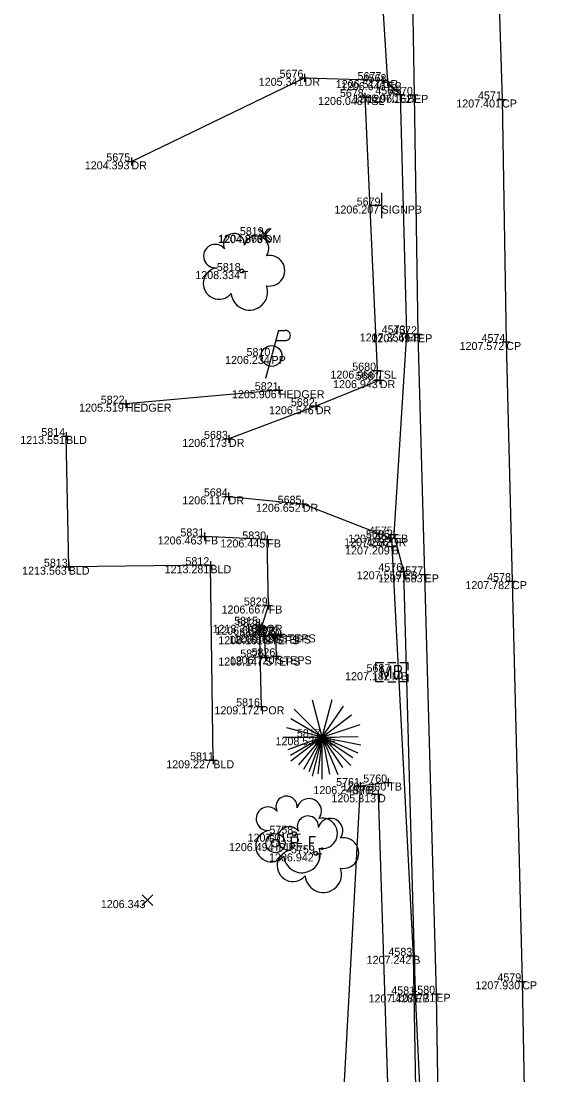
# Model space of a CAD drawing. Extents: x 2044996 to 2050343, y 455232 to 458054.
# Drawn here: x 2047573.4 to 2047639.7, y 456784 to 456915.7 of the extents above; entities that cross this region are included whole.
import ezdxf

# ---------------------------------------------------------------- set-up
doc = ezdxf.new("R2010")
doc.units = 0
for name, color, linetype in [('BD_X_Building', 7, 'Continuous'), ('BD_X_Porch_or_Deck', 7, 'Continuous'), ('DR_X_Ditch', 7, 'Continuous'), ('DT_X_Contour_Minor', 7, 'Continuous'), ('DT_X_Contour_Text', 7, 'Continuous'), ('DT_X_Island', 7, 'Continuous'), ('DT_X_Spot_Elev', 7, 'Continuous'), ('DT_X_Triangles', 7, 'Continuous'), ('DT_X_Void', 7, 'Continuous'), ('PV_X_COP', 7, 'Continuous'), ('PV_X_Driveway', 7, 'Continuous'), ('PV_X_EOP', 7, 'Continuous'), ('PV_X_Shoulder_Aggregate', 7, 'Continuous'), ('PV_X_Steps', 7, 'Continuous'), ('RD_X_Cells', 7, 'Continuous'), ('SN_X_Public', 7, 'Continuous'), ('SV_X_Break_Lines', 7, 'Continuous'), ('SV_X_Toe_of_Slope', 7, 'Continuous'), ('SV_X_Top_of_Bank', 7, 'Continuous'), ('UT_X_Electric_Cells', 7, 'Continuous'), ('VG_X_Cells', 7, 'Continuous'), ('VG_X_Flower_Bed', 7, 'Continuous'), ('VG_X_Shrub_Line_Lt', 7, 'Continuous'), ('XS_X_Ground_Line', 7, 'Continuous')]:
    doc.layers.add(name, color=color, linetype=linetype)

msp = doc.modelspace()

# ---------------------------------------------------------------- linework, layer by layer
at = {"layer": 'BD_X_Building'}
msp.add_lwpolyline([(2047597.43, 456823.32), (2047597.07, 456847.69), (2047579.37, 456847.51), (2047579.04, 456863.84)], dxfattribs=at)
at = {"layer": 'BD_X_Porch_or_Deck'}
msp.add_lwpolyline([(2047603.17, 456840.25), (2047603.41, 456830.06)], dxfattribs=at)
at = {"layer": 'DR_X_Ditch'}
msp.add_lwpolyline([(2047618, 456819.07), (2047619.27, 456780.34), (2047618.87, 456740.62)], dxfattribs=at)
at = {"layer": 'DT_X_Island'}
msp.add_circle((2047603.85, 456888.94), 0.2, dxfattribs=at)
msp.add_arc((2047604.65, 456888.94), 0.8, 90, 270, dxfattribs=at)
at = {"layer": 'DT_X_Spot_Elev'}
for p, q in [((2047603.23, 456888.33), (2047604.57, 456889.67)), ((2047603.23, 456889.67), (2047604.57, 456888.33)), ((2047588.54, 456805.19), (2047589.87, 456806.52)), ((2047588.54, 456806.52), (2047589.87, 456805.19))]:
    msp.add_line(p, q, dxfattribs=at)
at = {"layer": 'DT_X_Void'}
for p, q in [((2047608.83, 456909.1), (2047608.83, 456908.1)), ((2047618.6, 456908.81), (2047618.6, 456907.81)), ((2047608.33, 456908.6), (2047609.33, 456908.6)), ((2047608.83, 456908.6), (2047608.83, 456908.6)), ((2047618.1, 456908.31), (2047619.1, 456908.31)), ((2047618.6, 456908.31), (2047618.6, 456908.31)), ((2047618.7, 456908.05), (2047619.7, 456908.05)), ((2047619.2, 456908.55), (2047619.2, 456907.55)), ((2047619.2, 456908.05), (2047619.2, 456908.05)), ((2047615.86, 456906.2), (2047616.86, 456906.2)), ((2047616.36, 456906.7), (2047616.36, 456905.7)), ((2047616.36, 456906.2), (2047616.36, 456906.2)), ((2047620.26, 456906.51), (2047621.26, 456906.51)), ((2047620.76, 456907.01), (2047620.76, 456906.01)), ((2047620.76, 456906.51), (2047620.76, 456906.51)), ((2047622, 456906.46), (2047623, 456906.46)), ((2047622.5, 456906.96), (2047622.5, 456905.96)), ((2047622.5, 456906.46), (2047622.5, 456906.46)), ((2047633.49, 456906.39), (2047633.49, 456905.39)), ((2047632.99, 456905.89), (2047633.99, 456905.89)), ((2047633.49, 456905.89), (2047633.49, 456905.89)), ((2047586.7, 456898.16), (2047587.7, 456898.16)), ((2047587.2, 456898.66), (2047587.2, 456897.66)), ((2047587.2, 456898.16), (2047587.2, 456898.16)), ((2047621.56, 456877.15), (2047621.56, 456876.15)), ((2047622.99, 456877.05), (2047622.99, 456876.05)), ((2047621.06, 456876.65), (2047622.06, 456876.65)), ((2047621.56, 456876.65), (2047621.56, 456876.65)), ((2047622.49, 456876.55), (2047623.49, 456876.55)), ((2047622.99, 456876.55), (2047622.99, 456876.55)), ((2047634.02, 456876.09), (2047634.02, 456875.09)), ((2047633.52, 456875.59), (2047634.52, 456875.59)), ((2047634.02, 456875.59), (2047634.02, 456875.59)), ((2047617.4, 456872.01), (2047618.4, 456872.01)), ((2047617.9, 456872.51), (2047617.9, 456871.51)), ((2047617.9, 456872.01), (2047617.9, 456872.01)), ((2047617.72, 456870.82), (2047618.72, 456870.82)), ((2047618.22, 456871.32), (2047618.22, 456870.32)), ((2047618.22, 456870.82), (2047618.22, 456870.82)), ((2047605.1, 456869.56), (2047606.1, 456869.56)), ((2047605.6, 456870.06), (2047605.6, 456869.06)), ((2047605.6, 456869.56), (2047605.6, 456869.56)), ((2047585.99, 456867.88), (2047586.99, 456867.88)), ((2047586.49, 456868.38), (2047586.49, 456867.38)), ((2047586.49, 456867.88), (2047586.49, 456867.88)), ((2047610.23, 456868.06), (2047610.23, 456867.06)), ((2047609.73, 456867.56), (2047610.73, 456867.56)), ((2047610.23, 456867.56), (2047610.23, 456867.56)), ((2047579.04, 456864.34), (2047579.04, 456863.34)), ((2047599.38, 456863.98), (2047599.38, 456862.98)), ((2047578.54, 456863.84), (2047579.54, 456863.84)), ((2047579.04, 456863.84), (2047579.04, 456863.84)), ((2047598.88, 456863.48), (2047599.88, 456863.48)), ((2047599.38, 456863.48), (2047599.38, 456863.48)), ((2047598.84, 456856.3), (2047599.84, 456856.3)), ((2047599.34, 456856.8), (2047599.34, 456855.8)), ((2047599.34, 456856.3), (2047599.34, 456856.3)), ((2047608.1, 456855.37), (2047609.1, 456855.37)), ((2047608.6, 456855.87), (2047608.6, 456854.87)), ((2047608.6, 456855.37), (2047608.6, 456855.37)), ((2047595.82, 456851.29), (2047596.82, 456851.29)), ((2047596.32, 456851.79), (2047596.32, 456850.79)), ((2047596.32, 456851.29), (2047596.32, 456851.29)), ((2047603.67, 456850.91), (2047604.67, 456850.91)), ((2047604.17, 456851.41), (2047604.17, 456850.41)), ((2047604.17, 456850.91), (2047604.17, 456850.91)), ((2047619.11, 456851.07), (2047620.11, 456851.07)), ((2047619.49, 456851.52), (2047620.49, 456851.52)), ((2047619.61, 456851.57), (2047619.61, 456850.57)), ((2047619.61, 456851.07), (2047619.61, 456851.07)), ((2047619.99, 456852.02), (2047619.99, 456851.02)), ((2047619.99, 456851.52), (2047619.99, 456851.52)), ((2047619.21, 456850.04), (2047620.21, 456850.04)), ((2047619.71, 456850.54), (2047619.71, 456849.54)), ((2047619.71, 456850.04), (2047619.71, 456850.04)), ((2047597.07, 456848.19), (2047597.07, 456847.19)), ((2047578.87, 456847.51), (2047579.87, 456847.51)), ((2047579.37, 456848.01), (2047579.37, 456847.01)), ((2047579.37, 456847.51), (2047579.37, 456847.51)), ((2047596.57, 456847.69), (2047597.57, 456847.69)), ((2047597.07, 456847.69), (2047597.07, 456847.69)), ((2047620.67, 456846.94), (2047621.67, 456846.94)), ((2047621.17, 456847.44), (2047621.17, 456846.44)), ((2047621.17, 456846.94), (2047621.17, 456846.94)), ((2047623.82, 456847.05), (2047623.82, 456846.05)), ((2047623.32, 456846.55), (2047624.32, 456846.55)), ((2047623.82, 456846.55), (2047623.82, 456846.55)), ((2047634.24, 456845.71), (2047635.24, 456845.71)), ((2047634.74, 456846.21), (2047634.74, 456845.21)), ((2047634.74, 456845.71), (2047634.74, 456845.71)), ((2047604.34, 456843.16), (2047604.34, 456842.16)), ((2047603.84, 456842.66), (2047604.84, 456842.66)), ((2047604.34, 456842.66), (2047604.34, 456842.66)), ((2047602.67, 456840.25), (2047603.67, 456840.25)), ((2047603.17, 456840.75), (2047603.17, 456839.75)), ((2047603.17, 456840.25), (2047603.17, 456840.25)), ((2047603.51, 456840.52), (2047603.51, 456839.52)), ((2047603.01, 456840.02), (2047604.01, 456840.02)), ((2047603.51, 456840.02), (2047603.51, 456840.02)), ((2047603.77, 456839.32), (2047603.77, 456838.32)), ((2047604.74, 456838.91), (2047605.74, 456838.91)), ((2047605.24, 456839.41), (2047605.24, 456838.41)), ((2047605.24, 456838.91), (2047605.24, 456838.91)), ((2047605.32, 456839.06), (2047606.32, 456839.06)), ((2047605.82, 456839.56), (2047605.82, 456838.56)), ((2047605.82, 456839.06), (2047605.82, 456839.06)), ((2047603.27, 456838.82), (2047604.27, 456838.82)), ((2047603.77, 456838.82), (2047603.77, 456838.82)), ((2047603.93, 456836.66), (2047603.93, 456835.66)), ((2047604.83, 456836.32), (2047605.83, 456836.32)), ((2047605.33, 456836.82), (2047605.33, 456835.82)), ((2047605.33, 456836.32), (2047605.33, 456836.32)), ((2047603.43, 456836.16), (2047604.43, 456836.16)), ((2047603.93, 456836.16), (2047603.93, 456836.16)), ((2047602.91, 456830.06), (2047603.91, 456830.06)), ((2047603.41, 456830.56), (2047603.41, 456829.56)), ((2047603.41, 456830.06), (2047603.41, 456830.06)), ((2047596.93, 456823.32), (2047597.93, 456823.32)), ((2047597.43, 456823.82), (2047597.43, 456822.82)), ((2047597.43, 456823.32), (2047597.43, 456823.32)), ((2047615.77, 456820.6), (2047615.77, 456819.6)), ((2047618.78, 456820.54), (2047619.78, 456820.54)), ((2047619.28, 456821.04), (2047619.28, 456820.04)), ((2047619.28, 456820.54), (2047619.28, 456820.54)), ((2047615.27, 456820.1), (2047616.27, 456820.1)), ((2047615.77, 456820.1), (2047615.77, 456820.1)), ((2047618, 456819.57), (2047618, 456818.57)), ((2047617.5, 456819.07), (2047618.5, 456819.07)), ((2047618, 456819.07), (2047618, 456819.07)), ((2047622.41, 456799.39), (2047622.41, 456798.39)), ((2047621.91, 456798.89), (2047622.91, 456798.89)), ((2047622.41, 456798.89), (2047622.41, 456798.89)), ((2047635.51, 456795.7), (2047636.51, 456795.7)), ((2047636.01, 456796.2), (2047636.01, 456795.2)), ((2047636.01, 456795.7), (2047636.01, 456795.7)), ((2047622.66, 456794.56), (2047622.66, 456793.56)), ((2047624.78, 456794.15), (2047625.78, 456794.15)), ((2047625.28, 456794.65), (2047625.28, 456793.65)), ((2047625.28, 456794.15), (2047625.28, 456794.15)), ((2047622.16, 456794.06), (2047623.16, 456794.06)), ((2047622.66, 456794.06), (2047622.66, 456794.06))]:
    msp.add_line(p, q, dxfattribs=at)
at = {"layer": 'PV_X_COP'}
msp.add_lwpolyline([(2047630.62, 457032.63), (2047631.64, 456997.55), (2047632.38, 456961.54), (2047632.83, 456926.92), (2047633.49, 456905.89), (2047634.02, 456875.59), (2047634.74, 456845.71), (2047636.01, 456795.7), (2047636.79, 456753.22), (2047638.14, 456705.84), (2047638.65, 456684.97), (2047639.72, 456638.63)], dxfattribs=at)
at = {"layer": 'PV_X_Driveway'}
for points in [[(2047587.2, 456898.16), (2047608.83, 456908.6), (2047618.6, 456908.31)], [(2047618.22, 456870.82), (2047610.23, 456867.56), (2047599.38, 456863.48)], [(2047599.34, 456856.3), (2047608.6, 456855.37), (2047619.61, 456851.07)]]:
    msp.add_lwpolyline(points, dxfattribs=at)
at = {"layer": 'PV_X_EOP'}
for p, q in [((2047622.09, 456930.85), (2047622.5, 456906.46)), ((2047622.5, 456906.46), (2047622.99, 456876.55)), ((2047622.99, 456876.55), (2047623.82, 456846.55)), ((2047623.82, 456846.55), (2047625.28, 456794.15)), ((2047625.28, 456794.15), (2047625.91, 456753.93))]:
    msp.add_line(p, q, dxfattribs=at)
at = {"layer": 'PV_X_Shoulder_Aggregate'}
for p, q in [((2047617.76, 456929.81), (2047619.2, 456908.05)), ((2047619.2, 456908.05), (2047620.76, 456906.51)), ((2047620.76, 456906.51), (2047621.56, 456876.65)), ((2047621.56, 456876.65), (2047619.99, 456851.52)), ((2047619.99, 456851.52), (2047621.17, 456846.94)), ((2047621.17, 456846.94), (2047622.66, 456794.06)), ((2047622.66, 456794.06), (2047624.53, 456753.98))]:
    msp.add_line(p, q, dxfattribs=at)
at = {"layer": 'PV_X_Steps'}
msp.add_lwpolyline([(2047605.82, 456839.06), (2047603.77, 456838.82), (2047603.93, 456836.16), (2047605.33, 456836.32), (2047605.24, 456838.91)], dxfattribs=at)
at = {"layer": 'RD_X_Cells'}
for p, q in [((2047619.21, 456835.55), (2047620.21, 456835.55)), ((2047619.72, 456834.33), (2047619.72, 456834.33)), ((2047619.21, 456833.11), (2047620.21, 456833.11))]:
    msp.add_line(p, q, dxfattribs=at)
for points in [[(2047617.72, 456834.58), (2047617.72, 456835.55), (2047618.69, 456835.55)], [(2047618.43, 456833.53), (2047618.43, 456835.13), (2047619.01, 456833.53), (2047619.56, 456835.13), (2047619.56, 456833.53)], [(2047620.74, 456834.4), (2047620.81, 456834.46), (2047620.84, 456834.5), (2047620.87, 456834.54), (2047620.88, 456834.56), (2047620.91, 456834.62), (2047620.92, 456834.65), (2047620.95, 456834.74), (2047620.95, 456834.78), (2047620.95, 456834.83), (2047620.93, 456834.91), (2047620.91, 456834.97), (2047620.87, 456835.02), (2047620.81, 456835.07), (2047620.76, 456835.09), (2047620.73, 456835.11), (2047620.67, 456835.13), (2047620.05, 456835.13), (2047620.05, 456833.53), (2047620.74, 456833.53), (2047620.83, 456833.58), (2047620.91, 456833.65), (2047620.97, 456833.75), (2047621.01, 456833.86), (2047621.02, 456833.97), (2047621.02, 456834.05), (2047621, 456834.12), (2047620.95, 456834.24), (2047620.88, 456834.31), (2047620.74, 456834.4), (2047620.05, 456834.4)], [(2047620.73, 456835.55), (2047621.72, 456835.55), (2047621.72, 456834.58)], [(2047618.69, 456833.11), (2047617.72, 456833.11), (2047617.72, 456834.08)], [(2047621.72, 456834.08), (2047621.72, 456833.11), (2047620.73, 456833.11)]]:
    msp.add_lwpolyline(points, dxfattribs=at)
at = {"layer": 'SN_X_Public'}
for p, q in [((2047618.44, 456894.24), (2047618.44, 456891.04)), ((2047618.44, 456892.64), (2047616.84, 456892.64))]:
    msp.add_line(p, q, dxfattribs=at)
at = {"layer": 'SV_X_Break_Lines'}
msp.add_lwpolyline([(2047619.71, 456850.04), (2047622.41, 456798.89), (2047623.17, 456753.78), (2047624.47, 456706.91), (2047623.93, 456684.68)], dxfattribs=at)
at = {"layer": 'SV_X_Toe_of_Slope'}
msp.add_lwpolyline([(2047616.36, 456906.2), (2047617.9, 456872.01)], dxfattribs=at)
at = {"layer": 'SV_X_Top_of_Bank'}
msp.add_lwpolyline([(2047619.28, 456820.54), (2047615.77, 456820.1), (2047613.47, 456777.8), (2047614.89, 456741.81)], dxfattribs=at)
at = {"layer": 'UT_X_Electric_Cells'}
for p, q in [((2047605.56, 456877.04), (2047603.95, 456871.04)), ((2047605.22, 456875.76), (2047606.41, 456875.76)), ((2047605.56, 456877.04), (2047606.41, 456877.04))]:
    msp.add_line(p, q, dxfattribs=at)
msp.add_circle((2047604.7, 456873.84), 1.3, dxfattribs=at)
msp.add_arc((2047606.42, 456876.4), 0.638, 268.8767, 91.1233, dxfattribs=at)
at = {"layer": 'VG_X_Cells'}
for p, q in [((2047611.03, 456826.2), (2047607.54, 456829.69)), ((2047611.03, 456826.2), (2047609.8, 456830.82)), ((2047611.03, 456826.2), (2047612.29, 456830.9)), ((2047611.03, 456826.2), (2047613.69, 456830.09)), ((2047611.03, 456826.2), (2047607.13, 456828.5)), ((2047611.03, 456826.2), (2047614.69, 456829.01)), ((2047611.03, 456826.2), (2047606.62, 456827.39)), ((2047611.03, 456826.2), (2047615.77, 456827.81)), ((2047606.1, 456826.2), (2047611.03, 456826.2)), ((2047611.03, 456826.2), (2047606.74, 456824.64)), ((2047611.03, 456826.2), (2047607.05, 456823.92)), ((2047611.03, 456826.2), (2047607.13, 456823.21)), ((2047611.03, 456826.2), (2047608.09, 456822.74)), ((2047611.03, 456826.2), (2047608.71, 456822.19)), ((2047611.03, 456826.2), (2047609.37, 456821.86)), ((2047611.03, 456826.2), (2047609.77, 456821.35)), ((2047611.03, 456826.2), (2047610.49, 456821.61)), ((2047611.03, 456826.2), (2047615.54, 456826.3)), ((2047611.03, 456820.96), (2047611.03, 456826.2)), ((2047611.03, 456826.2), (2047611.95, 456821.57)), ((2047611.03, 456826.2), (2047612.97, 456821.54)), ((2047611.03, 456826.2), (2047613.57, 456822.41)), ((2047611.03, 456826.2), (2047614.62, 456822.68)), ((2047611.03, 456826.2), (2047614.85, 456823.65)), ((2047611.03, 456826.2), (2047615.5, 456824.26)), ((2047611.03, 456826.2), (2047615.86, 456825.25))]:
    msp.add_line(p, q, dxfattribs=at)
for centre in [(2047600.99, 456884.45), (2047607.55, 456814.15), (2047610.23, 456811.69)]:
    msp.add_circle(centre, 0.24, dxfattribs=at)
for centre, radius, start, end in [((2047600.01, 456887.82), 1.32, 354.0047, 205.9741), ((2047597.68, 456886.32), 1.47, 39.0625, 279.5412), ((2047602.82, 456887.28), 1.55, 323.83, 165.0376), ((2047604.45, 456884.49), 1.91, 259.1453, 101.4596), ((2047598.14, 456882.9), 1.97, 96.1722, 320.5737), ((2047601.94, 456881.85), 2.28, 184.9476, 19.4572), ((2047606.57, 456817.52), 1.32, 354.0047, 205.9741), ((2047609.38, 456816.98), 1.55, 323.83, 165.0376), ((2047604.25, 456816.02), 1.47, 39.0625, 279.5412), ((2047609.24, 456815.05), 1.32, 354.0047, 205.9741), ((2047612.05, 456814.51), 1.55, 323.83, 165.0376), ((2047611.02, 456814.19), 1.91, 259.1453, 101.4596), ((2047604.7, 456812.6), 1.97, 96.1722, 320.5737), ((2047606.92, 456813.55), 1.47, 39.0625, 279.5412), ((2047613.69, 456811.72), 1.91, 259.1453, 101.4596), ((2047607.37, 456810.14), 1.97, 96.1722, 320.5737), ((2047608.5, 456811.55), 2.28, 184.9476, 19.4572), ((2047611.17, 456809.08), 2.28, 184.9476, 19.4572)]:
    msp.add_arc(centre, radius, start, end, dxfattribs=at)
at = {"layer": 'VG_X_Flower_Bed'}
msp.add_lwpolyline([(2047603.51, 456840.02), (2047604.34, 456842.66), (2047604.17, 456850.91), (2047596.32, 456851.29)], dxfattribs=at)
at = {"layer": 'VG_X_Shrub_Line_Lt'}
msp.add_lwpolyline([(2047605.6, 456869.56), (2047586.49, 456867.88)], dxfattribs=at)
at = {"layer": 'XS_X_Ground_Line'}
for points in [[(2047607.18, 456812.17), (2047607.18, 456813.77), (2047607.71, 456813.77), (2047607.77, 456813.76), (2047607.84, 456813.73), (2047607.88, 456813.71), (2047607.91, 456813.68), (2047607.95, 456813.62), (2047607.99, 456813.56), (2047608.01, 456813.46), (2047608.01, 456813.31), (2047608, 456813.26), (2047607.98, 456813.18), (2047607.93, 456813.09), (2047607.89, 456813.05), (2047607.86, 456813.03), (2047607.8, 456813), (2047607.71, 456812.99), (2047607.18, 456812.99)], [(2047610.19, 456813.77), (2047609.43, 456813.77), (2047609.43, 456812.17)], [(2047609.43, 456812.99), (2047609.97, 456812.99)], [(2047608.83, 456812.39), (2047608.88, 456812.39), (2047608.91, 456812.36), (2047608.95, 456812.31), (2047608.95, 456812.25), (2047608.91, 456812.2), (2047608.88, 456812.17), (2047608.83, 456812.17), (2047608.79, 456812.2), (2047608.76, 456812.25), (2047608.76, 456812.31), (2047608.79, 456812.36), (2047608.83, 456812.39)], [(2047610.97, 456812.39), (2047611.03, 456812.39), (2047611.06, 456812.36), (2047611.1, 456812.31), (2047611.1, 456812.25), (2047611.06, 456812.2), (2047611.03, 456812.17), (2047610.97, 456812.17), (2047610.94, 456812.2), (2047610.91, 456812.25), (2047610.91, 456812.31), (2047610.94, 456812.36), (2047610.97, 456812.39)]]:
    msp.add_lwpolyline(points, dxfattribs=at)
for radius in [1.2, 0.495]:
    msp.add_circle((2047605.19, 456812.97), radius, dxfattribs=at)

# ---------------------------------------------------------------- texts
at = {"layer": 'DT_X_Contour_Minor'}
for s, p in [('1205.341', (2047603.11, 456907.6)), ('1206.517', (2047612.72, 456907.31)), ('1206.646', (2047613.36, 456907.05)), ('1206.048', (2047610.52, 456905.2)), ('1206.960', (2047614.92, 456905.51)), ('1207.162', (2047616.67, 456905.46)), ('1207.401', (2047627.78, 456904.89)), ('1204.393', (2047581.38, 456897.16)), ('1206.207', (2047612.56, 456891.64)), ('1204.876', (2047598.01, 456887.94)), ('1204.866', (2047598.06, 456888)), ('1208.334', (2047595.18, 456883.45)), ('1207.356', (2047615.72, 456875.65)), ('1207.494', (2047617.18, 456875.55)), ('1207.572', (2047628.19, 456874.59)), ('1206.234', (2047598.9, 456872.84)), ('1206.956', (2047612.06, 456871.01)), ('1206.943', (2047612.39, 456869.82)), ('1205.906', (2047599.76, 456868.56)), ('1205.519', (2047580.67, 456866.88)), ('1206.546', (2047604.39, 456866.56)), ('1213.551', (2047573.32, 456862.84)), ('1206.173', (2047593.56, 456862.48)), ('1206.117', (2047593.56, 456855.3)), ('1206.652', (2047602.76, 456854.37)), ('1206.463', (2047590.49, 456850.29)), ('1206.445', (2047598.33, 456849.91)), ('1207.256', (2047613.77, 456850.07)), ('1207.391', (2047614.27, 456850.52)), ('1207.209', (2047613.89, 456849.04)), ('1213.563', (2047573.55, 456846.51)), ('1213.281', (2047591.35, 456846.69)), ('1207.559', (2047615.35, 456845.94)), ('1207.683', (2047617.99, 456845.55)), ('1207.782', (2047628.91, 456844.71)), ('1206.667', (2047598.46, 456841.66)), ('1213.218', (2047597.34, 456839.25)), ('1206.682', (2047597.67, 456839.02)), ('1206.808', (2047599.4, 456837.91)), ('1206.720', (2047599.99, 456838.06)), ('1208.161', (2047598.05, 456837.82)), ('1206.720', (2047599.49, 456835.32)), ('1208.147', (2047598.05, 456835.16)), ('1207.182', (2047613.89, 456833.33)), ('1209.172', (2047597.57, 456829.06)), ('1208.532', (2047605.2, 456825.2)), ('1209.227', (2047591.55, 456822.32)), ('1206.380', (2047613.45, 456819.54)), ('1206.248', (2047609.93, 456819.1)), ('1205.313', (2047612.18, 456818.07)), ('1207.015', (2047601.71, 456813.15)), ('1206.494', (2047599.38, 456811.97)), ('1206.942', (2047604.39, 456810.69)), ('1206.343', (2047583.38, 456804.85)), ('1207.242', (2047616.58, 456797.89)), ('1207.930', (2047630.17, 456794.7)), ('1207.771', (2047619.56, 456793.15)), ('1207.428', (2047616.82, 456793.06))]:
    msp.add_text(s, height=1, dxfattribs=at).set_placement(p)
at = {"layer": 'DT_X_Contour_Text'}
for s, p in [('DR', (2047608.83, 456907.6)), ('DR', (2047618.6, 456907.31)), ('EB', (2047619.2, 456907.05)), ('TSL', (2047616.36, 456905.2)), ('EB', (2047620.76, 456905.51)), ('EP', (2047622.5, 456905.46)), ('CP', (2047633.49, 456904.89)), ('DR', (2047587.2, 456897.16)), ('SIGNPB', (2047618.44, 456891.64)), ('DM', (2047603.85, 456887.94)), ('T', (2047600.99, 456883.45)), ('EB', (2047621.56, 456875.65)), ('EP', (2047622.99, 456875.55)), ('CP', (2047634.02, 456874.59)), ('PP', (2047604.7, 456872.84)), ('TSL', (2047617.9, 456871.01)), ('DR', (2047618.22, 456869.82)), ('HEDGER', (2047605.6, 456868.56)), ('HEDGER', (2047586.49, 456866.88)), ('DR', (2047610.23, 456866.56)), ('BLD', (2047579.04, 456862.84)), ('DR', (2047599.38, 456862.48)), ('DR', (2047599.34, 456855.3)), ('DR', (2047608.6, 456854.37)), ('FB', (2047596.32, 456850.29)), ('FB', (2047604.17, 456849.91)), ('DR', (2047619.61, 456850.07)), ('EB', (2047619.99, 456850.52)), ('B', (2047619.71, 456849.04)), ('BLD', (2047579.37, 456846.51)), ('BLD', (2047597.07, 456846.69)), ('EB', (2047621.17, 456845.94)), ('EP', (2047623.82, 456845.55)), ('CP', (2047634.74, 456844.71)), ('FB', (2047604.34, 456841.66)), ('POR', (2047603.17, 456839.25)), ('FB', (2047603.51, 456839.02)), ('STEPS', (2047605.24, 456837.91)), ('STEPS', (2047605.82, 456838.06)), ('STEPS', (2047603.77, 456837.82)), ('STEPS', (2047605.33, 456835.32)), ('STEPS', (2047603.93, 456835.16)), ('MB', (2047619.72, 456833.33)), ('POR', (2047603.41, 456829.06)), ('TE', (2047611.03, 456825.2)), ('BLD', (2047597.43, 456822.32)), ('TB', (2047619.28, 456819.54)), ('TB', (2047615.77, 456819.1)), ('D', (2047618, 456818.07)), ('T', (2047607.55, 456813.15)), ('IPIPE', (2047605.19, 456811.97)), ('T', (2047610.23, 456810.69)), ('B', (2047622.41, 456797.89)), ('CP', (2047636.01, 456794.7)), ('EP', (2047625.28, 456793.15)), ('EB', (2047622.66, 456793.06))]:
    msp.add_text(s, height=1, dxfattribs=at).set_placement(p)
at = {"layer": 'DT_X_Triangles'}
for s, p in [('5676', (2047605.71, 456908.6)), ('5677', (2047615.44, 456908.31)), ('4568', (2047616.08, 456908.05)), ('4569', (2047617.66, 456906.51)), ('4570', (2047619.38, 456906.46)), ('5678', (2047613.24, 456906.2)), ('4571', (2047630.49, 456905.89)), ('5675', (2047584.07, 456898.16)), ('5679', (2047615.34, 456892.64)), ('5819', (2047600.75, 456888.94)), ('5818', (2047597.87, 456884.45)), ('4573', (2047618.46, 456876.65)), ('4572', (2047619.88, 456876.55)), ('4574', (2047630.93, 456875.59)), ('5810', (2047601.58, 456873.84)), ('5680', (2047614.78, 456872.01)), ('5681', (2047615.22, 456870.82)), ('5821', (2047602.61, 456869.56)), ('5822', (2047583.37, 456867.88)), ('5682', (2047607.12, 456867.56)), ('5814', (2047575.95, 456863.84)), ('5683', (2047596.27, 456863.48)), ('5684', (2047596.25, 456856.3)), ('5685', (2047605.47, 456855.37)), ('5831', (2047593.32, 456851.29)), ('5686', (2047616.49, 456851.07)), ('4575', (2047616.86, 456851.52)), ('5830', (2047601.05, 456850.91)), ('4582', (2047616.59, 456850.04)), ('5813', (2047576.27, 456847.51)), ('5812', (2047593.95, 456847.69)), ('4576', (2047618.05, 456846.94)), ('4577', (2047620.66, 456846.55)), ('4578', (2047631.63, 456845.71)), ('5829', (2047601.24, 456842.66)), ('5815', (2047600.04, 456840.25)), ('5828', (2047600.39, 456840.02)), ('5824', (2047600.68, 456838.82)), ('5827', (2047602.08, 456838.91)), ('5823', (2047602.72, 456839.06)), ('5825', (2047600.8, 456836.16)), ('5826', (2047602.2, 456836.32)), ('5687', (2047616.56, 456834.33)), ('5816', (2047600.28, 456830.06)), ('5817', (2047607.87, 456826.2)), ('5811', (2047594.53, 456823.32)), ('5761', (2047612.77, 456820.1)), ('5760', (2047616.16, 456820.54)), ('5762', (2047614.89, 456819.07)), ('5758', (2047604.44, 456814.15)), ('6', (2047604.39, 456812.97)), ('5759', (2047607.13, 456811.69)), ('4583', (2047619.3, 456798.89)), ('4579', (2047632.91, 456795.7)), ('4581', (2047619.66, 456794.06)), ('4580', (2047622.16, 456794.15))]:
    msp.add_text(s, height=1, dxfattribs=at).set_placement(p)

doc.saveas('drawing.dxf')
